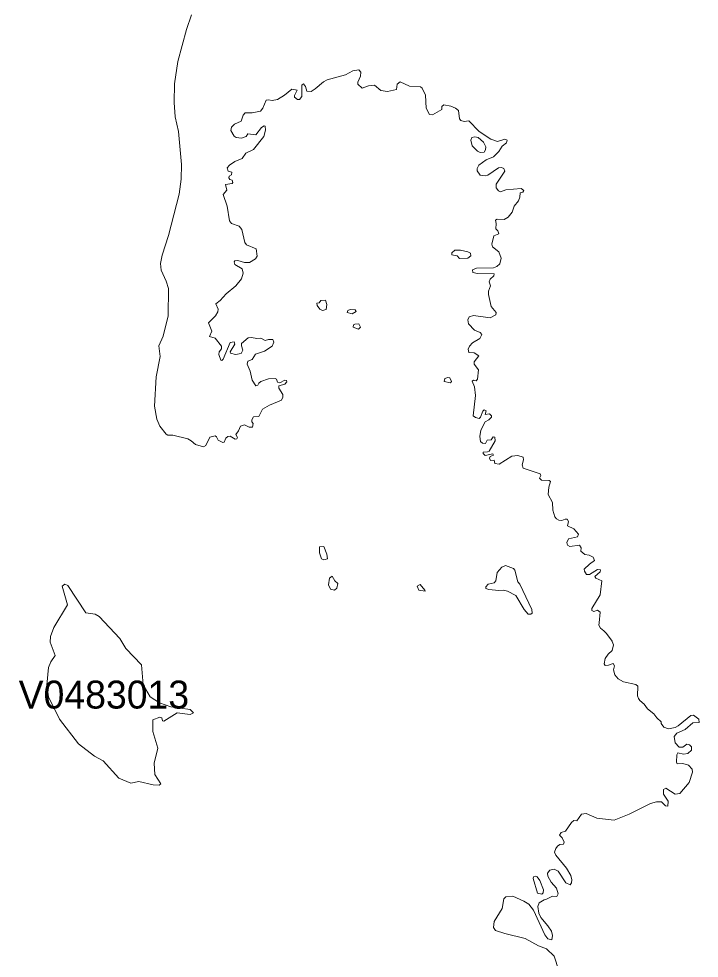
# Model space of a CAD drawing. Extents: x 369010 to 735936, y 6377141 to 6616555.
# Drawn here: x 399474 to 401908, y 6487089 to 6490450 of the extents above; entities that cross this region are included whole.
import ezdxf
from ezdxf.enums import TextEntityAlignment as Align

# ---------------------------------------------------------------- set-up
doc = ezdxf.new("R2010")
doc.units = 0
doc.header["$LTSCALE"] = 40
doc.layers.add('3', color=7, linetype='Continuous', lineweight=13)
doc.layers.add('4', color=7, linetype='Continuous')

msp = doc.modelspace()

# ---------------------------------------------------------------- linework, layer by layer
at = {"layer": '3'}
for points in [[(400091.86, 6490463.4), (400074.15, 6490411.26), (400042.7, 6490296.9), (400030.62, 6490216.79), (400030.29, 6490150.59), (400033.27, 6490098.96), (400044.69, 6490046.49), (400055.78, 6489928.49), (400054.45, 6489875.36), (400047.34, 6489822.23), (400009.6, 6489674.6), (399986.6, 6489603.93), (399981.3, 6489574.31), (399983.62, 6489550.81), (400001.66, 6489511.42), (400008.94, 6489485.27), (400008.61, 6489386.79), (399990.9, 6489314.8), (399974.85, 6489280.04), (399979.48, 6489241.31), (399964.92, 6489169.15), (399959.12, 6489064.22), (399967.23, 6489017.06), (399978.16, 6488992.73), (400001, 6488963.6), (400007.62, 6488959.96), (400025.32, 6488959.96), (400078.45, 6488946.88), (400090.86, 6488940.26), (400105.93, 6488926.86), (400134.72, 6488918.42), (400142.67, 6488923.22), (400157.4, 6488952.51), (400176.1, 6488957.31), (400181.73, 6488953.5), (400186.86, 6488942.58), (400204.23, 6488933.81), (400208.87, 6488935.46)], [(400227.24, 6489726.41), (400218.96, 6489779.53), (400204.57, 6489821.24), (400218.14, 6489836.63), (400212.84, 6489857.32), (400237, 6489860.63), (400239.32, 6489864.11), (400237.67, 6489872.88), (400228.56, 6489875.03), (400224.92, 6489880.16), (400226.41, 6489886.95), (400235.02, 6489891.41), (400236.34, 6489901.51), (400222.61, 6489905.15), (400219.3, 6489915.91), (400227.57, 6489925.84), (400246.6, 6489939.24), (400272.42, 6489950.33), (400285.99, 6489968.7), (400313.14, 6489981.78), (400350.54, 6490028.12), (400356.99, 6490051.62), (400355.67, 6490065.19), (400352.2, 6490066.19), (400342.6, 6490060.56), (400321.58, 6490034.57), (400292.78, 6490038.55), (400287.81, 6490028.78), (400270.44, 6490023.15), (400250.91, 6490025.47), (400243.96, 6490030.11), (400232.87, 6490049.47), (400234.85, 6490062.21), (400245.61, 6490072.31), (400269.94, 6490083.4), (400277.06, 6490104.42), (400283.35, 6490113.35), (400309.16, 6490112.69), (400338.29, 6490119.15), (400346.57, 6490129.74), (400358.65, 6490158.54), (400366.92, 6490160.19), (400380, 6490157.54), (400399.69, 6490160.52), (400424.52, 6490176.91), (400450.84, 6490198.26), (400469.21, 6490194.62), (400460.27, 6490175.58), (400460.6, 6490168.8), (400470.53, 6490160.52), (400477.98, 6490160.85), (400486.92, 6490172.27), (400486.25, 6490211.66), (400492.05, 6490216.96), (400499.66, 6490207.69), (400504.62, 6490191.31), (400519.35, 6490189.65), (400534.25, 6490199.42), (400563.54, 6490224.74), (400576.78, 6490231.69), (400642.32, 6490249.07), (400668.47, 6490263.8), (400689.82, 6490267.11), (400697.27, 6490258.17), (400696.11, 6490244.43), (400686.51, 6490222.42), (400687.18, 6490215.97), (400701.91, 6490201.9), (400724.91, 6490209.35), (400745.93, 6490211.66), (400768.77, 6490192.96), (400792.44, 6490189.65), (400825.54, 6490196.27), (400827.52, 6490215.64), (400838.28, 6490224.08), (400872.04, 6490208.35), (400911.1, 6490206.37), (400917.06, 6490201.57), (400928.81, 6490176.91), (400931.46, 6490129.74), (400942.88, 6490107.07), (400954.3, 6490105.74), (400986.57, 6490125.44), (400987.07, 6490136.36), (400994.35, 6490142.15), (401019.67, 6490137.52), (401035.73, 6490130.4), (401046.48, 6490121.13), (401050.13, 6490092.34), (401055.09, 6490086.38), (401066.51, 6490082.57), (401083.23, 6490084.72), (401120.96, 6490046.16), (401162.83, 6490019.18), (401185.84, 6490010.74), (401211.99, 6490018.52), (401220.59, 6490015.05), (401217.95, 6490005.45), (401202.55, 6489993.7), (401190.8, 6489974.66)], [(401190.8, 6489974.66), (401172.1, 6489955.96), (401145.79, 6489945.2), (401119.64, 6489925.51), (401113.02, 6489914.58), (401113.02, 6489905.81), (401124.11, 6489890.42), (401143.8, 6489888.43), (401151.74, 6489890.75), (401190.14, 6489915.91), (401200.24, 6489917.89), (401208.68, 6489914.58), (401211.99, 6489905.15), (401181.87, 6489857.65), (401181.2, 6489844.58), (401189.48, 6489833.65), (401196.93, 6489830.67), (401215.96, 6489838.29), (401270.74, 6489842.59), (401280.51, 6489835.97), (401277.03, 6489829.35), (401266.77, 6489826.54), (401265.94, 6489811.31), (401261.14, 6489797.9), (401246.41, 6489778.87), (401238.3, 6489757.69), (401224.9, 6489740.47), (401210, 6489731.37), (401184.51, 6489732.36), (401178.56, 6489729.72), (401181.87, 6489717.3), (401180.54, 6489698.27), (401187.49, 6489691.32), (401191.13, 6489680.89), (401173.43, 6489672.78), (401166.14, 6489643.82), (401168.13, 6489633.39), (401190.47, 6489615.68), (401199.24, 6489593.67), (401194.61, 6489572.98), (401183.85, 6489563.88), (401171.44, 6489558.59), (401111.69, 6489556.93), (401096.96, 6489551.14), (401098.62, 6489541.87), (401115.33, 6489537.9), (401174.09, 6489537.07), (401172.76, 6489530.45), (401160.19, 6489517.71), (401157.04, 6489508.44), (401161.18, 6489494.37), (401154.39, 6489474.67), (401153.73, 6489462.92), (401163.83, 6489420.22), (401181.87, 6489399.37), (401179.88, 6489390.1), (401160.19, 6489380.01), (401100.6, 6489387.79), (401084.55, 6489383.81), (401080.58, 6489373.06), (401082.9, 6489358.33), (401103.58, 6489335.98), (401124.11, 6489327.54), (401130.06, 6489320.59), (401123.28, 6489305.53), (401096.3, 6489290.14), (401085.87, 6489279.05), (401080.91, 6489267.46), (401083.23, 6489256.37), (401102.59, 6489254.06), (401119.31, 6489244.29), (401102.59, 6489222.28), (401102.26, 6489213.67), (401118.31, 6489193.48), (401115.33, 6489160.38), (401109.38, 6489154.76), (401100.6, 6489157.07), (401095.31, 6489153.76), (401104.25, 6489132.41), (401107.06, 6489102.29), (401099.28, 6489029.14), (401107.06, 6489023.35), (401120.63, 6489020.04), (401125.43, 6489024.34), (401133.71, 6489046.18), (401138.01, 6489050.49), (401145.79, 6489047.51), (401142.48, 6489033.77), (401158.2, 6489036.42), (401164.49, 6489029.8), (401164.82, 6489024.34), (401155.39, 6489014.41), (401142.15, 6489007.29), (401126.09, 6488978.33), (401122.95, 6488955.49), (401125.76, 6488936.79), (401132.71, 6488931.82), (401142.81, 6488930.17), (401149.76, 6488941.59), (401163.5, 6488942.91)], [(400208.87, 6488935.46), (400214.83, 6488949.53), (400221.28, 6488955.82), (400229.89, 6488956.48), (400248.26, 6488946.22), (400254.05, 6488947.21), (400256.04, 6488951.52), (400250.24, 6488962.61), (400260.34, 6488975.02), (400266.63, 6488992.06), (400281.03, 6488996.7), (400298.08, 6488988.59), (400309.83, 6488989.25), (400312.14, 6489001.66), (400307.18, 6489007.62), (400307.51, 6489014.41), (400313.8, 6489025.17), (400332.83, 6489027.15), (400345.91, 6489052.8), (400370.24, 6489067.87), (400413.43, 6489085.57), (400418.73, 6489096.33), (400418.07, 6489105.27), (400404.33, 6489128.44), (400404.66, 6489136.38), (400425.18, 6489143), (400432.46, 6489150.45), (400431.14, 6489155.42), (400425.84, 6489157.4), (400407.47, 6489147.8), (400399.03, 6489149.46), (400395.39, 6489160.71), (400391.09, 6489163.2), (400367.59, 6489161.04), (400339.95, 6489152.44), (400332.5, 6489146.15), (400329.19, 6489138.37), (400322.24, 6489137.05), (400308.5, 6489156.74), (400301.72, 6489189.51), (400291.12, 6489213.67), (400293.77, 6489224.6), (400309.16, 6489230.72), (400320.09, 6489250.09), (400353.19, 6489260.35), (400380.66, 6489278.39), (400386.29, 6489293.12), (400382.32, 6489301.89), (400367.59, 6489302.22), (400355.67, 6489298.58), (400339.62, 6489306.52), (400324.89, 6489305.53), (400305.85, 6489309.83), (400294.1, 6489308.18), (400271.1, 6489288.15), (400270.44, 6489279.38), (400275.07, 6489263.99), (400269.94, 6489252.4), (400249.58, 6489248.43), (400230.88, 6489253.06), (400230.55, 6489258.36), (400246.6, 6489286.17), (400243.96, 6489294.44), (400230.55, 6489291.46), (400204.57, 6489231.71), (400200.1, 6489227.25), (400196.12, 6489228.9), (400189.84, 6489249.09), (400190.17, 6489257.7), (400198.77, 6489268.79), (400198.77, 6489279.05), (400176.43, 6489306.52), (400156.07, 6489312.48), (400164.35, 6489332.34), (400152.76, 6489361.97), (400177.09, 6489386.46), (400186.19, 6489401.85), (400186.86, 6489411.12), (400179.08, 6489429.82), (400194.14, 6489441.9), (400215.49, 6489466.23), (400250.58, 6489494.7), (400270.77, 6489519.03), (400276.73, 6489540.21), (400272.75, 6489554.61), (400246.27, 6489570.83), (400244.29, 6489579.94), (400246.93, 6489583.25), (400257.36, 6489584.9), (400281.03, 6489577.62), (400298.74, 6489577.62), (400320.09, 6489590.36), (400326.54, 6489600.29), (400323.56, 6489626.11), (400288.81, 6489640.84), (400282.68, 6489649.12), (400271.76, 6489696.28), (400262.66, 6489707.54), (400235.02, 6489717.3), (400227.24, 6489726.41)], [(401163.5, 6488942.91), (401170.78, 6488953.5), (401176.24, 6488952.84), (401177.89, 6488939.6), (401156.38, 6488903.35), (401151.08, 6488900.04), (401135.36, 6488899.05), (401134.7, 6488894.09), (401141.81, 6488887.63), (401169.12, 6488893.42), (401171.44, 6488888.46), (401160.52, 6488883.33), (401157.54, 6488877.7), (401161.51, 6488869.59), (401173.76, 6488870.92), (401176.57, 6488858.67), (401191.96, 6488856.68), (401236.98, 6488884.65), (401258.99, 6488886.97), (401278.19, 6488881.67), (401279.18, 6488872.07), (401275.05, 6488853.87), (401277.86, 6488841.62), (401338.6, 6488821.6), (401341.25, 6488815.47), (401336.94, 6488805.87), (401343.23, 6488799.09), (401371.37, 6488797.43), (401376.33, 6488794.12), (401369.88, 6488774.26), (401367.4, 6488747.95), (401383.12, 6488718.65), (401383.78, 6488691.18), (401391.39, 6488667.84), (401397.02, 6488660.39), (401405.46, 6488655.76), (401405.63, 6488655.76), (401415.89, 6488654.93), (401428.14, 6488659.9), (401435.92, 6488659.07), (401440.22, 6488651.13), (401437.24, 6488635.4), (401458.92, 6488624.65), (401475.64, 6488605.28), (401472.99, 6488596.18), (401440.22, 6488589.23), (401434.26, 6488576.15), (401436.25, 6488566.55), (401445.51, 6488561.42), (401479.28, 6488566.22), (401485.4, 6488556.79), (401484.08, 6488545.37), (401498.31, 6488532.79), (401514.03, 6488530.14), (401528.43, 6488523.03), (401533.07, 6488511.28), (401515.03, 6488499.03), (401496.32, 6488480.99), (401496.99, 6488473.21), (401505.1, 6488461.62), (401515.03, 6488461.62), (401544.15, 6488479.66), (401554.58, 6488478.34), (401552.93, 6488471.22), (401534.89, 6488454.84), (401537.87, 6488448.55), (401558.88, 6488438.79), (401552.93, 6488388.31), (401523.8, 6488339.81), (401523.14, 6488333.19), (401530.75, 6488329.22), (401543.82, 6488333.86), (401553.92, 6488326.57), (401549.95, 6488288.51), (401549.29, 6488280.07), (401555.24, 6488269.64), (401566.33, 6488260.54), (401575.77, 6488250.44), (401595.96, 6488222.47), (401595.96, 6488222.31), (401601.25, 6488209.56), (401596.95, 6488189.54), (401581.56, 6488176.13), (401571.3, 6488161.4), (401567.49, 6488142.37), (401571.63, 6488136.24), (401583.54, 6488137.07), (401600.26, 6488143.53), (401604.4, 6488134.75), (401601.75, 6488121.02), (401606.38, 6488102.15), (401617.97, 6488088.58), (401636.84, 6488077.49), (401680.86, 6488067.73), (401687.98, 6488061.44), (401687.15, 6488027.18), (401690.79, 6488018.07), (401695.59, 6488010.46), (401711.15, 6487997.55), (401722.57, 6487981.33)], [(401722.57, 6487981.33), (401745.9, 6487963.13), (401756.33, 6487948.56), (401771.39, 6487934.83), (401772.05, 6487928.04), (401781.49, 6487914.8), (401798.2, 6487909.67), (401821.87, 6487914.47), (401832.96, 6487920.1), (401878.14, 6487957.5), (401887.74, 6487958.49), (401906.11, 6487944.42), (401907.77, 6487932.18), (401885.09, 6487930.36), (401857.29, 6487906.69), (401827.99, 6487894.28), (401818.23, 6487882.03), (401821.54, 6487859.19), (401836.27, 6487843.47), (401848.68, 6487843.8), (401864.07, 6487854.22), (401873.01, 6487852.24), (401880.46, 6487845.45), (401880.13, 6487833.21), (401866.72, 6487821.46), (401851.99, 6487819.14), (401831.3, 6487823.11), (401828.33, 6487815.83), (401827, 6487789.68), (401829.32, 6487783.72), (401848.68, 6487785.38), (401870.03, 6487779.09), (401882.78, 6487765.35), (401884.1, 6487754.26), (401871.36, 6487717.85), (401838.92, 6487678.46), (401821.87, 6487675.48), (401788.77, 6487697.16), (401780.49, 6487692.53), (401779.83, 6487675.15), (401796.55, 6487650.66), (401795.22, 6487632.95), (401787.11, 6487633.61), (401772.38, 6487648.34), (401755.01, 6487648.67), (401733.99, 6487642.05), (401657.19, 6487603.49), (401603.74, 6487582.47), (401541.84, 6487589.42), (401503.77, 6487606.8), (401486.39, 6487604.48), (401470.34, 6487580.15), (401459.91, 6487580.81), (401450.98, 6487574.19), (401429.79, 6487543.08), (401414.57, 6487537.95), (401407.78, 6487529.34), (401417.54, 6487519.58), (401425.16, 6487503.85), (401422.51, 6487496.9), (401409.1, 6487495.91), (401401.16, 6487489.95), (401394.7, 6487480.68), (401390.4, 6487468.27), (401394.7, 6487457.18), (401432.94, 6487411.01), (401448.99, 6487384.52), (401452.63, 6487368.64), (401450.65, 6487358.21), (401445.85, 6487351.59), (401431.28, 6487358.21), (401403.15, 6487399.92), (401388.75, 6487406.7), (401374.02, 6487403.39), (401365.08, 6487392.97), (401366.4, 6487382.54), (401377.99, 6487360.86), (401397.85, 6487339.84), (401403.81, 6487318.82), (401398.18, 6487309.39), (401382.79, 6487310.38), (401359.62, 6487298.3), (401353.66, 6487297.97), (401335.62, 6487286.38), (401330.65, 6487273.31), (401334.3, 6487249.97), (401340.92, 6487234.25), (401366.57, 6487204.62), (401379.31, 6487185.75), (401383.45, 6487170.03), (401380.47, 6487154.97), (401366.4, 6487157.95), (401355.98, 6487172.68), (401315.59, 6487260.56), (401298.55, 6487282.08), (401280.51, 6487293.33), (401240.95, 6487310.71), (401215.96, 6487308.06), (401208.68, 6487300.78), (401202.55, 6487267.02)], [(401202.55, 6487267.02), (401174.75, 6487219.85), (401172.1, 6487198.5), (401178.89, 6487188.07), (401212.15, 6487177.15), (401285.47, 6487159.6), (401333.3, 6487133.29), (401361.27, 6487121.87), (401388.75, 6487096.22), (401405.46, 6487045.08)]]:
    msp.add_lwpolyline(points, dxfattribs=at)
for points in [[(401105.24, 6490027.79), (401093.98, 6490024.81), (401091, 6490015.38), (401095.64, 6489995.35), (401115, 6489975.66), (401124.77, 6489971.02), (401138.01, 6489972.68), (401142.81, 6489980.95), (401144.13, 6489991.38), (401136.35, 6490007.76), (401116.99, 6490024.81)], [(401033.08, 6489622.3), (401022.49, 6489612.7), (401023.48, 6489605.59), (401042.18, 6489601.62), (401050.46, 6489592.35), (401079.59, 6489593.01), (401091.34, 6489601.62), (401089.18, 6489611.38), (401079.59, 6489616.35), (401054.1, 6489622.3)], [(400550.47, 6489411.12), (400560.23, 6489405.82), (400573.14, 6489409.14), (400575.46, 6489427.51), (400570.49, 6489442.57), (400554.11, 6489441.57), (400548.81, 6489433.8), (400540.04, 6489432.8), (400541.04, 6489424.53)], [(400658.71, 6489409.47), (400651.1, 6489406.49), (400648.45, 6489399.37), (400665.83, 6489394.07), (400680.89, 6489402.18), (400677.08, 6489408.14)], [(400688.83, 6489339.62), (400696.61, 6489346.24), (400690.49, 6489358.33), (400675.42, 6489357.66), (400671.12, 6489354.68), (400669.47, 6489346.57)], [(401008.09, 6489165.84), (400998.32, 6489162.2), (400996.01, 6489152.11), (401018.02, 6489146.81), (401021.82, 6489152.44), (401016.36, 6489165.51)], [(400565.53, 6488562.09), (400550.14, 6488561.09), (400549.48, 6488538.75), (400556.76, 6488517.73), (400564.87, 6488513.76), (400578.27, 6488517.07), (400576.29, 6488533.78)], [(401214.64, 6488493.24), (401202.22, 6488487.61), (401184.85, 6488468.58), (401179.88, 6488438.79), (401174.75, 6488432.16), (401153.07, 6488427.2), (401145.12, 6488417.77), (401145.12, 6488411.81), (401155.06, 6488408), (401191.47, 6488403.7), (401208.18, 6488405.02), (401221.92, 6488401.71), (401252.37, 6488386.65), (401281.5, 6488335.84), (401296.23, 6488319.79), (401305.17, 6488319.46), (401310.46, 6488323.43), (401309.14, 6488336.17), (401265.78, 6488427.53), (401259.32, 6488435.81), (401248.4, 6488477.18), (401244.1, 6488482.97)], [(400604.09, 6488438.95), (400595.32, 6488455.5), (400585.89, 6488448.88), (400581.91, 6488425.05), (400588.87, 6488408.99), (400603.26, 6488406.02), (400612.04, 6488412.47), (400615.35, 6488429.85)], [(399762.01, 6488311.84), (399746.62, 6488319.79), (399713.85, 6488324.09), (399649.63, 6488421.74), (399638.38, 6488427.53), (399628.94, 6488419.75), (399647.64, 6488353.55), (399599.48, 6488272.29), (399587.9, 6488240.01), (399586.57, 6488219.16), (399604.28, 6488171.83), (399588.56, 6488149.65), (399580.78, 6488128.63), (399574.49, 6488065.74), (399580.45, 6488023.7), (399619.18, 6487944.42), (399687.7, 6487855.55), (399744.63, 6487811.69), (399776.08, 6487795.47), (399831.85, 6487732.58), (399875.21, 6487715.53), (399903.35, 6487721.49), (399955.15, 6487708.42), (399975.51, 6487707.75), (399981.96, 6487712.22), (399960.78, 6487746.32), (399958.46, 6487787.03), (399971.87, 6487839.83), (399953.5, 6487899.74), (399953.83, 6487941.11), (399978.82, 6487951.21), (399985.27, 6487949.22), (399987.92, 6487938.47), (399992.89, 6487937.14), (400041.05, 6487966.27), (400086.89, 6487961.14), (400099.31, 6487966.93), (400087.55, 6487978.85), (400018.04, 6487988.61), (399976.83, 6488002.68), (399943.73, 6488023.7), (399918.74, 6488066.73), (399913.11, 6488138.73), (399856.51, 6488197.15), (399835.82, 6488232.57)], [(400926.83, 6488405.35), (400909.78, 6488426.04), (400899.35, 6488420.08), (400904.81, 6488405.68), (400927.16, 6488401.38)], [(401337.94, 6487367.15), (401328.17, 6487379.89), (401322.88, 6487382.54), (401315.26, 6487380.22), (401314.27, 6487373.93), (401329, 6487321.14), (401344.56, 6487317.83), (401350.02, 6487323.12), (401351.34, 6487333.55)]]:
    msp.add_lwpolyline(points, close=True, dxfattribs=at)

# ---------------------------------------------------------------- texts
at = {"layer": '4'}
msp.add_text('V0483013', height=100, dxfattribs=at).set_placement((399778.27, 6487981.93), align=Align.CENTER)

doc.saveas('drawing.dxf')
